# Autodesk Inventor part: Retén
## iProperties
Shininess: 64.0
Length Units: 11272
Angle Units: 11279
Time Units: 11290
Mass Units: 11286
Length Display Precision: 3
Angle Display Precision: 2
Compacted: True
Part Number: Retén
Document SubType Name: Modeling
Created: 2005-06
Designer: Alek
Manufacturer: Standard
Standards Organization: Custom
Density: 0.0
Volumn: 0.0
Area: 0.0
PropertySet Name: Model Information
Control State: 0
Master: False
Checked Out: False
Author: Alek
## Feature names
1. Extrusion1
2. Hole1
3. Circular Pattern1
